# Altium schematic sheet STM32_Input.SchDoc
size A; SheetNumber: 1; SheetTotal: 5
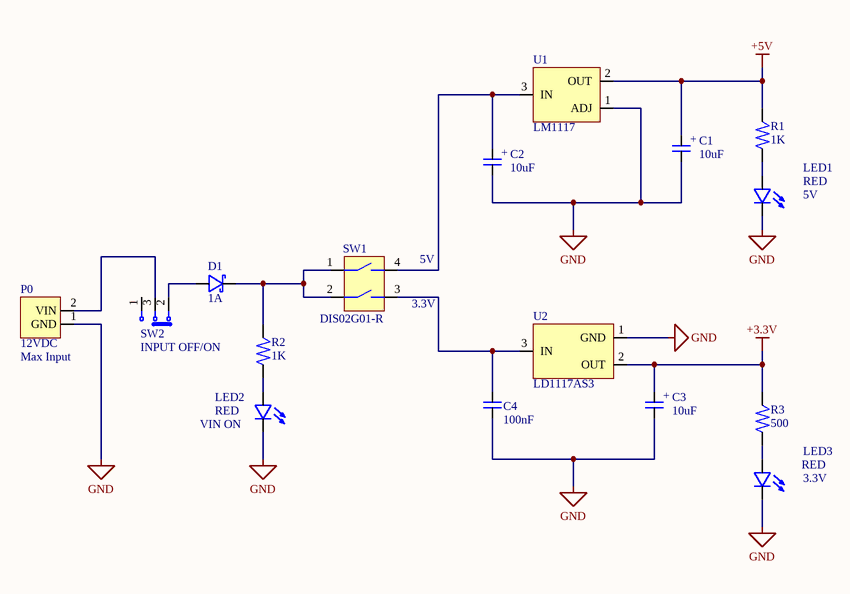
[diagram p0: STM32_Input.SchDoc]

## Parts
C1  10uF  [SMT_CAP_EL_CHANG_VT1E100MC054000CE0]
C2  10uF  [SMT_CAP_EL_CHANG_VT1E100MC054000CE0]
C3  10uF  [SMT_CAP_EL_CHANG_VT1E100MC054000CE0]
C4  100nF  [SMT_CAP_1206(3216)_SAMSUNG]
D1  1A  [SMT_DIODE_SCHTKY_SMB_ONSEMI]
LED1  RED  [DIOM2012X18N]
LED2  RED  [DIOM2012X18N]
LED3  RED  [DIOM2012X18N]
P0  12VDC  [THT_CON_WAFER_2P_STRAIGHT_A2001WV2-2P]
R1  1K  [SMT_RES_0805(2012)]
R2  1K  [SMT_RES_0805(2012)]
R3  500  [SMT_RES_0805(2012)]
SW1  DIS02G01-R  [SMT_SWITCH_DIP_DIS02G01-R]
SW2  INPUT OFF/ON  [THT_SSW_ESP1010]
U1  LM1117  [SOT230P700X180-4N]
U2  LD1117AS3  [SMT_VR_LD1117AS3]

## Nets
+3.3V: C3.1 R3.2 U2.2(OUT)
+5V: C1.1 R1.2 U1.2(OUT)
GND: C1.2 C2.2 C3.2 C4.1 LED1.2 LED2.2 LED3.2 P0.1(GND) U1.1(ADJ) U2.1(GND)
NetC2_1: C2.1 SW1.4 U1.3(IN)
NetC4_2: C4.2 SW1.3 U2.3(IN)
NetD1_1: D1.1 SW2.2
NetD1_2: D1.2 R2.2 SW1.1 SW1.2
NetLED1_1: LED1.1 R1.1
NetLED2_1: LED2.1 R2.1
NetLED3_1: LED3.1 R3.1
NetP0_2: P0.2(VIN) SW2.3

Not connected (* = marked no-connect by the designer): SW2 1

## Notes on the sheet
- 5V
- (near SW1) 5V
- (near SW1) 3.3V
- (near P0) Max Input
- (near LED2) VIN ON
- 3.3V

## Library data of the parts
C1-C3 = SMT_CAP_EL_CHANG_VT1E100MC054000CE0: SMT Capacitor Electrolytic 35V 10uF Pitch 1.3mm VT1E100MC054000CE0
C4 = SMT_CAP_1206(3216)_SAMSUNG: Ceramic Capacitor 1206(3216) Samsung CL31B104KBCNNNC 50VDC
D1 = SMT_DIODE_SCHTKY_SMB_ONSEMI: SMT Diode Schottky ONSEMI MODEL IF=1A VR=20V FV=0.6V MBRS120T3G
LED1-LED3 = SMT_LED_0805(2012): Led Diode 0805(2012) Cathode Mark, 20mA
P0 = THT_CON_WAFER_2P_STRAIGHT_A2001WV2-2P: Connector Wafer 2-Pins Pitch-2.0mm Straight Pins A2001WV2-2P
R1-R3 = SMT_RES_0805(2012): 0805(2012) Resistor 1/4-1/8W 150V 2A
SW1 = SMT_SWITCH_DIP_DIS02G01-R: DIP SMD Switch 2-Line 4-Pole 2.54Pitch Rating 25mA/24Vdc Height 0.70mm
SW2 = THT_SSW_ESP1010: Slide Switch ESP1010 12V 0.5A
U1 = LM1117_SOT-223: LM1117 SOT-223 5V HTC Voltage Regulator
U2 = SMT_VR_LD1117AS3: Voltage Regulator ST LD1117AS33TR 1A 3.3V 10Vmax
